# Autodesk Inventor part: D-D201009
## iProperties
Created: 2007-10
Part Number: D-D201009
Document SubType Name: Modeling
Designer: MM
Density: 7.85 g/cm^3
Mass: 1039.33 g
Surface Area: 1235.3 cm^2
Volume: 132.398 cm^3
Material: Steel
Description: TOP FRAME RIGHT SIDE PLATE
Component Category: Lower Component
Author: MM
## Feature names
1. Extrusion1
2. Extrusion2
3. Fillet1
4. Extrusion3
5. Extrusion4
6. Fillet4
7. Fillet5
8. Fillet6
9. Fillet7
10. Extrusion9
11. Chamfer2
12. Chamfer3
13. Fillet13
14. Fillet14
15. Extrusion10
16. Chamfer4
17. Fillet15
18. Fillet16
19. Fillet8
20. Shell1
21. Extrusion5
22. Extrusion6
23. Extrusion7
24. Extrusion8
25. Fillet9
26. Fillet10
27. Fillet11
28. Fillet12
29. Extrusion11
30. Fillet17
31. Fillet18
32. Extrusion12
33. Extrusion13
34. Fillet19
35. Fillet20
36. Extrusion14
37. Extrusion15
38. Fillet21
39. Fillet22
40. Fillet23
41. Hole1
42. Hole2
43. Hole3
44. Hole4
45. Extrusion17
46. Extrusion18
47. Extrusion19
